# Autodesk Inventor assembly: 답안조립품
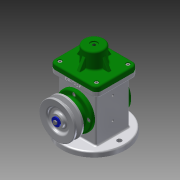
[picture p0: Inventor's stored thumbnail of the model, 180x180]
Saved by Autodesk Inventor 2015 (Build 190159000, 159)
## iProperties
Created: 2018-10
Part Number: 답안조립품
Document SubType Name: Assembly
Designer: pc
Author: pc
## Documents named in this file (18)
- C:\Users\pc\Desktop\481007V1059\답안조립품.iam
- C:\Users\pc\Desktop\481007V1059\본체.ipt
- C:\Users\pc\Desktop\481007V1059\V-벨트풀리.ipt
- C:\Users\pc\Desktop\481007V1059\덮개.ipt
- C:\Users\pc\Desktop\481007V1059\뒤커버.ipt
- C:\Users\pc\Desktop\481007V1059\링크.ipt
- C:\Users\pc\Desktop\481007V1059\베어링 17 x 40 x 12.ipt
- C:\Users\pc\Desktop\481007V1059\볼트 M4 x 8.ipt
- C:\Users\pc\Desktop\481007V1059\볼트 M4 x 10.ipt
- C:\Users\pc\Desktop\481007V1059\슬라이더.ipt
- C:\Users\pc\Desktop\481007V1059\앞커버.ipt
- C:\Users\pc\Desktop\481007V1059\오일 실 17 30 8.ipt
- C:\Users\pc\Desktop\481007V1059\와셔 4x16.ipt
- C:\Users\pc\Desktop\481007V1059\클레비스 핀 6 x 22.ipt
- 클레비스 핀 6 x 22.ipt
- C:\Users\pc\Desktop\481007V1059\키 4 x 4 x 12.ipt
- C:\Users\pc\Desktop\481007V1059\편심축.ipt
- C:\Users\pc\Desktop\481007V1059\E-링.ipt
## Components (2 placed, 2 different names)
1. V-벨트풀리:1 — 각도:1
2. E-링:1
## Component patterns: 구성요소 패턴 3:2 (2 elements)
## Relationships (1: Angle 1)
- 각도:1 [Angle]: V-벨트풀리:1
